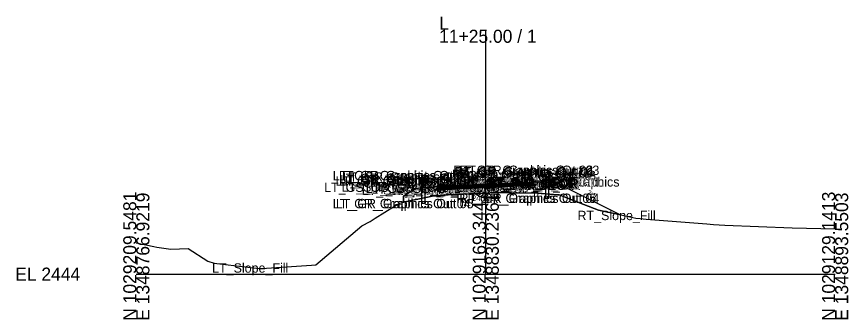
# Model space of a CAD drawing. Extents: x -26 to 1453, y -10 to 4527.
# Drawn here: x 1274.3 to 1452.8, y 1990.3 to 2055.2 of the extents above; entities that cross this region are included whole.
import ezdxf

# ---------------------------------------------------------------- set-up
doc = ezdxf.new("R2010")
doc.units = 0
for name, color, linetype in [('Default', 7, 'Continuous'), ('Exist Cross Section Cell', 7, 'Continuous'), ('Exist XS Center Line Elevation Label', 7, 'Continuous'), ('Exist XS Ground Line', 7, 'Continuous'), ('Old_Level_63', 7, 'Continuous'), ('Prop CMT Guardrail Graphics', 7, 'Continuous'), ('Prop CMT Pvmt Course 1', 7, 'Continuous'), ('Prop CMT Pvmt Course 2', 7, 'Continuous'), ('Prop CMT Pvmt Course 3', 7, 'Continuous'), ('Prop CMT Pvmt Surface', 7, 'Continuous'), ('Prop CMT Pvmt Surface Overlay', 7, 'Continuous'), ('Prop CMT Pvmt Surface Shoulder', 7, 'Continuous'), ('Prop CMT Shld Paved Course 1', 7, 'Continuous'), ('Prop CMT Shld Paved Course 2', 7, 'Continuous'), ('Prop CMT Shld Paved Course 3', 7, 'Continuous'), ('Prop CMT Slope Grass', 7, 'Continuous'), ('Prop CMT Subgrade Earthwork', 7, 'Continuous'), ('Prop XS Earthwork Shape', 7, 'Continuous'), ('Prop XS EOT Tick Mark', 7, 'Continuous'), ('Prop XS SE Text', 7, 'Continuous'), ('Prop XS Side Slope Text', 7, 'Continuous')]:
    doc.layers.add(name, color=color, linetype=linetype)

msp = doc.modelspace()

# ---------------------------------------------------------------- linework, layer by layer
at = {"layer": 'Exist Cross Section Cell'}
for p, q in [((1375, 2000), (1375, 2052.4)), ((1300, 2000), (1375, 2000)), ((1375, 2000), (1450, 2000))]:
    msp.add_line(p, q, dxfattribs=at)
at = {"layer": 'Exist XS Ground Line'}
msp.add_lwpolyline([(1300, 2006.72), (1303.79, 2005.91), (1304.43, 2005.81), (1307.43, 2005.32), (1311.12, 2005.49), (1315.38, 2002.81), (1316.72, 2002.34), (1323.93, 2001.52), (1326.4, 2001.23), (1326.9, 2001.24), (1337.6, 2001.93), (1338.56, 2001.99), (1348.39, 2010.34), (1350.16, 2011.3), (1351.24, 2012), (1355.41, 2014.6), (1356.47, 2015.24), (1358.38, 2015.65), (1363.86, 2016.78), (1364.45, 2016.82), (1367.83, 2017.06), (1373.21, 2017.31), (1375, 2017.39), (1376.77, 2017.47), (1380.1, 2017.44), (1386.25, 2017.36), (1390.4, 2017.03), (1390.76, 2017.02), (1393.86, 2015.8), (1399.18, 2013.69), (1404.02, 2012.72), (1407.24, 2012.02), (1408.17, 2011.91), (1409.41, 2011.81), (1422.43, 2010.75), (1423.9, 2010.61), (1426.35, 2010.5), (1440.81, 2009.94), (1450, 2009.69)], dxfattribs=at)
at = {"layer": 'Prop CMT Guardrail Graphics'}
for points in [[(1361.26, 2015.13), (1361.26, 2021.13)], [(1361.26, 2021.13), (1362.59, 2021.13), (1362.86, 2020.83)], [(1388.51, 2022.27), (1387.18, 2022.27), (1386.91, 2021.98)], [(1386.91, 2021.98), (1387.18, 2021.69)], [(1387.18, 2021.69), (1386.91, 2021.4)], [(1386.91, 2021.4), (1387.18, 2021.11), (1387.84, 2021.11)], [(1387.84, 2021.11), (1387.84, 2016.27)], [(1388.51, 2016.27), (1388.51, 2022.27)], [(1362.86, 2020.25), (1362.59, 2019.96), (1361.93, 2019.96)], [(1361.93, 2019.96), (1361.93, 2015.13)], [(1362.86, 2020.83), (1362.59, 2020.54)], [(1362.59, 2020.54), (1362.86, 2020.25)], [(1387.84, 2016.27), (1388.51, 2016.27)], [(1361.93, 2015.13), (1361.26, 2015.13)]]:
    msp.add_lwpolyline(points, dxfattribs=at)
at = {"layer": 'Prop CMT Pvmt Course 1'}
for points in [[(1374.96, 2019.29), (1364.96, 2018.79)], [(1374.96, 2019.29), (1384.96, 2019.79)], [(1384.96, 2019.54), (1374.96, 2019.04)], [(1374.96, 2019.17), (1374.96, 2019.29)], [(1374.96, 2019.17), (1374.96, 2019.29)], [(1384.96, 2019.79), (1384.96, 2019.54)], [(1364.96, 2018.54), (1374.96, 2019.04)], [(1364.96, 2018.79), (1364.96, 2018.54)], [(1374.96, 2019.04), (1374.96, 2019.17), (1374.96, 2019.17)], [(1374.96, 2019.04), (1374.96, 2019.17), (1374.96, 2019.17)]]:
    msp.add_lwpolyline(points, dxfattribs=at)
at = {"layer": 'Prop CMT Pvmt Course 2'}
for points in [[(1374.96, 2019.04), (1384.96, 2019.54)], [(1384.96, 2019.29), (1374.96, 2018.79)], [(1384.96, 2019.54), (1384.96, 2019.29)], [(1374.96, 2019.04), (1364.96, 2018.54)], [(1364.96, 2018.29), (1374.96, 2018.79)], [(1364.96, 2018.54), (1364.96, 2018.29)], [(1374.96, 2018.79), (1374.96, 2019.04)], [(1374.96, 2018.79), (1374.96, 2019.04)]]:
    msp.add_lwpolyline(points, dxfattribs=at)
at = {"layer": 'Prop CMT Pvmt Course 3'}
for points in [[(1374.96, 2018.79), (1384.96, 2019.29)], [(1384.96, 2019.29), (1384.96, 2019.04)], [(1374.96, 2018.79), (1364.96, 2018.29)], [(1364.96, 2018.04), (1374.96, 2018.54)], [(1364.96, 2018.29), (1364.96, 2018.04)], [(1384.96, 2019.04), (1374.96, 2018.54)], [(1374.96, 2018.54), (1374.96, 2018.79)], [(1374.96, 2018.54), (1374.96, 2018.79)]]:
    msp.add_lwpolyline(points, dxfattribs=at)
at = {"layer": 'Prop CMT Pvmt Surface'}
for points in [[(1374.96, 2019.29), (1364.96, 2018.79)], [(1374.96, 2019.29), (1384.96, 2019.79)]]:
    msp.add_lwpolyline(points, dxfattribs=at)
at = {"layer": 'Prop CMT Pvmt Surface Overlay'}
for points in [[(1374.96, 2019.29), (1364.96, 2018.79)], [(1374.96, 2019.29), (1384.96, 2019.79)]]:
    msp.add_lwpolyline(points, dxfattribs=at)
at = {"layer": 'Prop CMT Pvmt Surface Shoulder'}
for points in [[(1384.96, 2019.79), (1384.96, 2019.79)], [(1364.96, 2018.79), (1364.96, 2018.79)]]:
    msp.add_lwpolyline(points, dxfattribs=at)
at = {"layer": 'Prop CMT Shld Paved Course 1'}
for points in [[(1384.96, 2019.79), (1384.96, 2019.79), (1385.2, 2019.56)], [(1384.96, 2019.54), (1384.96, 2019.79)], [(1385.2, 2019.56), (1384.96, 2019.54)], [(1364.96, 2018.79), (1364.96, 2018.79), (1364.7, 2018.53)], [(1364.7, 2018.53), (1364.96, 2018.54)], [(1364.96, 2018.54), (1364.96, 2018.79)]]:
    msp.add_lwpolyline(points, dxfattribs=at)
at = {"layer": 'Prop CMT Shld Paved Course 2'}
for points in [[(1384.96, 2019.54), (1385.2, 2019.56), (1385.43, 2019.32)], [(1384.96, 2019.29), (1384.96, 2019.54)], [(1385.43, 2019.32), (1384.96, 2019.29)], [(1364.96, 2018.54), (1364.7, 2018.53), (1364.43, 2018.27)], [(1364.43, 2018.27), (1364.96, 2018.29)], [(1364.96, 2018.29), (1364.96, 2018.54)]]:
    msp.add_lwpolyline(points, dxfattribs=at)
at = {"layer": 'Prop CMT Shld Paved Course 3'}
for points in [[(1384.96, 2019.29), (1385.43, 2019.32)], [(1384.96, 2019.04), (1384.96, 2019.29)], [(1385.43, 2019.32), (1385.43, 2019.32)], [(1385.43, 2019.32), (1385.67, 2019.08)], [(1364.43, 2018.27), (1364.17, 2018)], [(1364.17, 2018), (1364.96, 2018.04)], [(1364.96, 2018.29), (1364.43, 2018.27)], [(1364.43, 2018.27), (1364.43, 2018.27)], [(1364.96, 2018.04), (1364.96, 2018.29)], [(1385.67, 2019.08), (1384.96, 2019.04)]]:
    msp.add_lwpolyline(points, dxfattribs=at)
at = {"layer": 'Prop CMT Slope Grass'}
for points in [[(1384.96, 2019.79), (1386.91, 2019.77)], [(1386.91, 2019.77), (1389.91, 2019.74)], [(1389.91, 2019.74), (1403.9, 2012.75)], [(1359.86, 2018.39), (1357.37, 2016.73)], [(1362.86, 2018.63), (1359.86, 2018.39)], [(1364.96, 2018.79), (1362.86, 2018.63)], [(1357.37, 2016.73), (1357.37, 2015.43)]]:
    msp.add_lwpolyline(points, dxfattribs=at)
at = {"layer": 'Prop CMT Subgrade Earthwork'}
for points in [[(1385.67, 2019.08), (1386.37, 2019.78)], [(1364.17, 2018), (1363.5, 2018.68)], [(1364.96, 2018.04), (1364.17, 2018)], [(1374.96, 2018.54), (1364.96, 2018.04)], [(1374.96, 2018.54), (1384.96, 2019.04)], [(1384.96, 2019.04), (1385.67, 2019.08)]]:
    msp.add_lwpolyline(points, dxfattribs=at)
at = {"layer": 'Prop XS Earthwork Shape'}
for points in [[(1374.96, 2018.54), (1384.96, 2019.04), (1385.67, 2019.08), (1386.37, 2019.78), (1386.91, 2019.77), (1389.91, 2019.74), (1403.9, 2012.75), (1399.18, 2013.69), (1393.86, 2015.8), (1390.76, 2017.02), (1390.4, 2017.03), (1386.25, 2017.36), (1380.1, 2017.44), (1376.77, 2017.47), (1375, 2017.39), (1373.21, 2017.31), (1367.83, 2017.06), (1364.45, 2016.82), (1363.86, 2016.78), (1358.38, 2015.65), (1357.37, 2015.43), (1357.37, 2016.73), (1359.86, 2018.39), (1362.86, 2018.63), (1363.5, 2018.68), (1364.17, 2018), (1364.96, 2018.04)], [(1389.91, 2019.74), (1403.9, 2012.75), (1399.18, 2013.69), (1393.86, 2015.8), (1390.76, 2017.02), (1390.4, 2017.03), (1386.25, 2017.36), (1380.1, 2017.44), (1376.77, 2017.47), (1375, 2017.39), (1373.21, 2017.31), (1367.83, 2017.06), (1364.45, 2016.82), (1363.86, 2016.78), (1358.38, 2015.65), (1357.37, 2015.43), (1357.37, 2016.73), (1359.86, 2018.39), (1362.86, 2018.63), (1363.5, 2018.68), (1364.17, 2018), (1364.96, 2018.04), (1374.96, 2018.54), (1384.96, 2019.04), (1385.67, 2019.08), (1386.37, 2019.78), (1386.91, 2019.77)]]:
    msp.add_lwpolyline(points, close=True, dxfattribs=at)
at = {"layer": 'Prop XS EOT Tick Mark'}
for points in [[(1364.96, 2018.79), (1364.96, 2019.79)], [(1384.96, 2019.79), (1384.96, 2020.79)]]:
    msp.add_lwpolyline(points, dxfattribs=at)

# ---------------------------------------------------------------- texts
at = {"layer": 'Default'}
msp.add_text('-', height=0.0001, dxfattribs=at).set_placement((1300, 2000))
at = {"layer": 'Exist Cross Section Cell'}
for s, p in [('L', (1365, 2052.4)), ('11+25.00 / 1', (1365, 2049.6)), ('EL 2444', (1274, 1998.6))]:
    msp.add_text(s, height=2.8, dxfattribs=at).set_placement(p)
for s, p in [('N 1029209.5481', (1300, 1990)), ('N 1029169.3447', (1375, 1990)), ('N 1029129.1413', (1450, 1990)), ('E 1348766.9219', (1302.8, 1990)), ('E 1348830.2361', (1377.8, 1990)), ('E 1348893.5503', (1452.8, 1990))]:
    msp.add_text(s, height=2.8, rotation=90, dxfattribs=at).set_placement(p)
at = {"layer": 'Exist XS Center Line Elevation Label'}
msp.add_text('2461.39', height=1.23, dxfattribs=at).set_placement((1372.04, 2015.66))
at = {"layer": 'Old_Level_63'}
for s, p in [('RT_GR_Graphics Out 02', (1368.03, 2021.27)), ('RT_GR_Graphics Out 09', (1368.03, 2020.69)), ('RT_GR_Graphics Out 01', (1368.32, 2020.98)), ('RT_GR_Graphics Out 03', (1369.36, 2021.27)), ('LT_GR_Graphics Out 03', (1342.16, 2020.13)), ('LT_GR_Graphics Out 06', (1342.78, 2018.96)), ('LT_GR_Graphics Out 02', (1343.49, 2020.13)), ('LT_GR_Graphics Out 09', (1343.49, 2019.54)), ('LT_GR_Graphics Out 07', (1343.49, 2018.96)), ('LT_GR_Graphics Out 08', (1343.76, 2019.25)), ('LT_GR_Graphics Out 01', (1344.33, 2019.83)), ('RT_GR_Graphics Out 08', (1367.76, 2020.4)), ('RT_GR_Graphics Out 07', (1368.03, 2020.11)), ('RT_GR_Graphics Out 06', (1368.65, 2020.11)), ('RT_TM_OEOT', (1375.85, 2019.79)), ('LT_GS_OS_GR_Face_Graphics', (1340.32, 2017.63)), ('LT_Sub_Trench_Out_DLT', (1344.06, 2017.68)), ('LT_GS_OS_CTL', (1349.23, 2017.39)), ('LT_PS3_Shelf_Out', (1350.42, 2017.27)), ('LT_PS3_OEOP', (1354.67, 2017.27)), ('LT_PS2_OEOP', (1354.93, 2017.53)), ('LT_PV2_OEOT', (1355.13, 2017.54)), ('LT_PV3_OEOT', (1355.13, 2017.29)), ('LT_PV1_OEOT', (1355.7, 2017.79)), ('LT_PS1_OEOP', (1355.76, 2017.79)), ('LT_TM_OEOT', (1355.9, 2018.79)), ('RT_PV1_OEEOP_W', (1362.9, 2018.17)), ('LT_PV1_OEEOP_W', (1362.94, 2018.17)), ('RT_Sub_OEEOP', (1364.12, 2017.54)), ('LT_Sub_OEEOP', (1364.17, 2017.54)), ('RT_PV2_OEEOP', (1364.22, 2018.04)), ('RT_PV3_OEEOP', (1364.22, 2017.79)), ('LT_PV2_OEEOP', (1364.27, 2018.04)), ('LT_PV3_OEEOP', (1364.27, 2017.79)), ('RT_GS_OS_GR_Face_Graphics', (1364.32, 2018.77)), ('RT_Sub_Trench_Out_DLT', (1366.89, 2018.78)), ('PV1_PGL_W', (1367.54, 2018.17)), ('PV1_PGL', (1369.43, 2018.29)), ('RT_Sub_Trench_Out', (1369.83, 2018.08)), ('RT_PS3_Shelf_Out', (1371.37, 2018.32)), ('RT_Sub_OEOT', (1374.99, 2018.04)), ('RT_PV2_OEOT', (1375.08, 2018.54)), ('RT_PV3_OEOT', (1375.08, 2018.29)), ('RT_PS2_OEOP', (1375.38, 2018.56)), ('RT_PS3_OEOP', (1375.62, 2018.32)), ('RT_PV1_OEOT', (1375.65, 2018.79)), ('RT_PS1_OEOP', (1375.71, 2018.79)), ('RT_GS_OS_CTL', (1379.23, 2018.74)), ('LT_Sub_Trench_Out', (1348.37, 2017)), ('LT_Sub_OEOT', (1355.04, 2017.04)), ('LT_GR_Graphics Out 04', (1342.16, 2014.13)), ('LT_GR_Graphics Out 05', (1342.82, 2014.13)), ('RT_GR_Graphics Out 05', (1368.69, 2015.27)), ('RT_GR_Graphics Out 04', (1369.36, 2015.27)), ('RT_Slope_Fill', (1394.7, 2011.58)), ('LT_Slope_Fill', (1316.27, 2000.32))]:
    msp.add_text(s, height=2, dxfattribs=at).set_placement(p)
at = {"layer": 'Prop XS SE Text'}
for p in [(1368.16, 2019.96), (1378.16, 2020.46)]:
    msp.add_text('0.050', height=1, rotation=2.8628, dxfattribs=at).set_placement(p)
at = {"layer": 'Prop XS Side Slope Text'}
for s, rotation, p in [('1.5:1', 33.6901, (1357.2, 2017.45)), ('2:1', 333.4316, (1396.69, 2017.19))]:
    msp.add_text(s, height=1, rotation=rotation, dxfattribs=at).set_placement(p)

doc.saveas('drawing.dxf')
